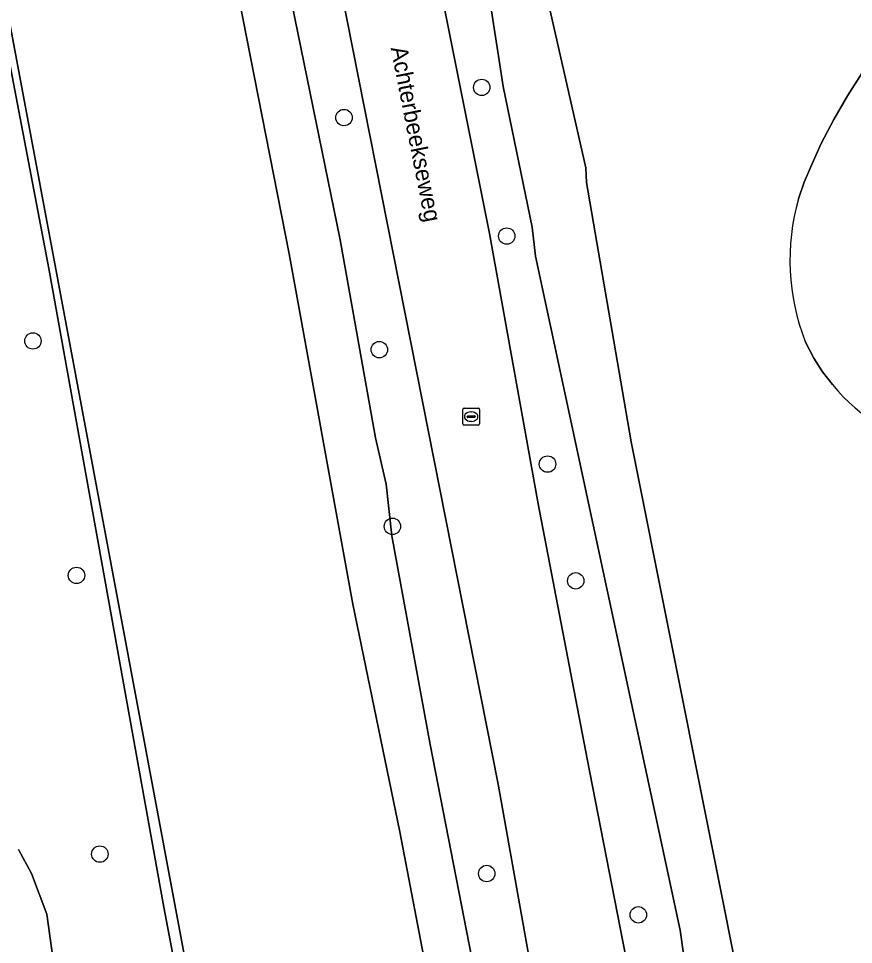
# Model space of a CAD drawing. Extents: x 162156 to 163172, y 378995 to 380779.
# Drawn here: x 162546.7 to 162596.4, y 380059.6 to 380114.8 of the extents above; entities that cross this region are included whole.
import ezdxf

# ---------------------------------------------------------------- set-up
doc = ezdxf.new("R2010")
doc.units = 0
for name, color, linetype in [('IMGEO_Boom', 7, 'Continuous'), ('IMGEO_Gemengd_bos', 7, 'Continuous'), ('IMGEO_Groenvoorziening', 7, 'Continuous'), ('IMGEO_Haag', 7, 'Continuous'), ('IMGEO_Hek', 7, 'Continuous'), ('IMGEO_Naaldbos', 7, 'Continuous'), ('IMGEO_Oever', 7, 'Continuous'), ('IMGEO_Openbare_ruimte_label', 7, 'Continuous'), ('IMGEO_Rijbaan_lokaal_gesloten', 7, 'Continuous'), ('IMGEO_Rioolput', 7, 'Continuous'), ('IMGEO_Waterloop', 7, 'Continuous')]:
    doc.layers.add(name, color=color, linetype=linetype)

msp = doc.modelspace()

# ---------------------------------------------------------------- linework, layer by layer
at = {"layer": 'IMGEO_Boom'}
for centre in [(162574.286, 380110.709), (162566.08, 380108.914), (162575.776, 380101.85), (162547.551, 380095.602), (162568.184, 380095.083), (162578.206, 380088.263), (162568.966, 380084.554), (162550.147, 380081.63), (162579.886, 380081.308), (162551.539, 380065.024), (162574.583, 380063.867), (162583.614, 380061.406)]:
    msp.add_circle(centre, 0.489, dxfattribs=at)
at = {"layer": 'IMGEO_Gemengd_bos'}
msp.add_lwpolyline([(162400.676, 380179.495), (162398.885, 380166.778), (162395.898, 380167.057), (162392.478, 380150.856), (162392.853, 380150.861), (162540.594, 380144.237), (162564.82, 380014.925), (162572.225, 380017.602), (162572.762, 380015.892), (162579.568, 380018.869), (162579.377, 380030.164), (162578.952, 380032.272), (162578.334, 380034.982), (162578.153, 380034.742), (162576.774, 380034.424), (162575.515, 380034.385), (162569.404, 380066.345), (162566.616, 380079.925), (162562.818, 380100.799), (162551.295, 380159.407)], dxfattribs=at)
at = {"layer": 'IMGEO_Groenvoorziening'}
for points in [[(162553.893, 380161.352), (162557.923, 380140.391), (162565.847, 380101.637), (162567.964, 380089.822), (162568.602, 380087.062), (162568.939, 380083.982), (162571.207, 380071.562), (162578.334, 380034.982), (162578.952, 380032.272), (162579.377, 380030.164), (162579.568, 380018.869)], [(162563.225, 380159.104), (162564.808, 380151.789), (162574.757, 380102.003), (162577.654, 380085.891), (162580.561, 380070.692), (162585.484, 380045.475), (162586.952, 380037.951), (162587.49, 380036.291)], [(162577.489, 380100.646), (162577.297, 380102.376), (162575.561, 380110.772), (162574.052, 380120.585), (162572.567, 380127.281), (162568.894, 380145.781), (162566.707, 380157.777)], [(162548.501, 380099.916), (162540.141, 380143.694), (162500, 380145.569), (162434.018, 380148.502), (162434.2, 380139.109), (162437.457, 380138.118), (162442.036, 380138.744), (162442.142, 380139.402), (162478.697, 380143.382), (162479.015, 380133.38), (162480.438, 380125.638), (162483.494, 380126.101), (162484.787, 380126.16)], [(162583.583, 380025.203), (162581.624, 380035.618), (162579.642, 380046.158), (162577.392, 380057.278), (162575.263, 380069.198), (162560.346, 380144.642)], [(162590.389, 380037.567), (162588.955, 380045.327), (162586.944, 380054.568), (162586.109, 380060.488), (162577.489, 380100.646)], [(162546.694, 380065.309), (162547.466, 380063.866), (162548.39, 380061.445), (162555.125, 380012.725), (162562.863, 380015.299), (162563.634, 380012.87), (162564.602, 380013.135), (162555.349, 380061.863), (162548.501, 380099.916)], [(162556.197, 380009.943), (162557.25, 380010.193), (162563.329, 380012.388), (162563.228, 380012.759), (162563.634, 380012.87), (162562.863, 380015.299), (162555.125, 380012.725), (162548.39, 380061.445), (162547.466, 380063.866), (162546.694, 380065.309)]]:
    msp.add_lwpolyline(points, dxfattribs=at)
msp.add_lwpolyline([(162540.594, 380144.237), (162392.853, 380150.861), (162392.478, 380150.856), (162392.372, 380150.353), (162434.018, 380148.502), (162500, 380145.569), (162540.141, 380143.694), (162548.501, 380099.916), (162555.349, 380061.863), (162564.602, 380013.135), (162564.772, 380013.181), (162564.864, 380012.844), (162565.189, 380012.97), (162565.117, 380013.339), (162564.82, 380014.925)], close=True, dxfattribs=at)
at = {"layer": 'IMGEO_Haag'}
msp.add_lwpolyline([(162540.594, 380144.237), (162392.853, 380150.861), (162392.478, 380150.856), (162392.372, 380150.353), (162434.018, 380148.502), (162500, 380145.569), (162540.141, 380143.694), (162548.501, 380099.916), (162555.349, 380061.863), (162564.602, 380013.135), (162564.772, 380013.181), (162564.864, 380012.844), (162565.189, 380012.97), (162565.117, 380013.339), (162564.82, 380014.925)], close=True, dxfattribs=at)
at = {"layer": 'IMGEO_Hek'}
msp.add_lwpolyline([(162392.372, 380150.353), (162434.018, 380148.502), (162500, 380145.569), (162540.141, 380143.694), (162548.501, 380099.916), (162555.349, 380061.863), (162564.602, 380013.135)], dxfattribs=at)
at = {"layer": 'IMGEO_Naaldbos'}
for points in [[(162598.999, 380160.213), (162591.971, 380160.192), (162585.021, 380160.577), (162577.372, 380161.631), (162570.251, 380162.647), (162569.587, 380158.112), (162574.693, 380132.607), (162578.254, 380115.715), (162580.493, 380105.908), (162580.519, 380105.048), (162583.194, 380089.584), (162590.102, 380054.964), (162591.376, 380047.324), (162593.189, 380038.48), (162594.802, 380031.543), (162603.357, 380032.993)], [(162593.163, 380104.065), (162593.501, 380105.073), (162593.87, 380105.936), (162594.512, 380107.359), (162595.253, 380108.803), (162596.066, 380110.209), (162596.949, 380111.572), (162597.899, 380112.888), (162599.054, 380114.328)], [(162595.176, 380093), (162594.593, 380093.77), (162594.075, 380094.585), (162593.559, 380095.572)]]:
    msp.add_lwpolyline(points, dxfattribs=at)
for centre, radius, start, end in [((162605.804, 380100.399), 13.162, 163.826, 201.5131), ((162604.151, 380100.411), 11.64, 219.5455, 257.5947)]:
    msp.add_arc(centre, radius, start, end, dxfattribs=at)
at = {"layer": 'IMGEO_Oever'}
for points in [[(162599.054, 380114.328), (162597.899, 380112.888), (162596.949, 380111.572), (162596.066, 380110.209), (162595.253, 380108.803), (162594.512, 380107.359), (162593.87, 380105.936), (162593.501, 380105.073), (162593.163, 380104.065)], [(162593.559, 380095.572), (162594.075, 380094.585), (162594.593, 380093.77), (162595.176, 380093)]]:
    msp.add_lwpolyline(points, dxfattribs=at)
for centre, radius, start, end in [((162605.804, 380100.399), 13.162, 163.826, 201.5131), ((162604.151, 380100.411), 11.64, 219.5455, 257.5947)]:
    msp.add_arc(centre, radius, start, end, dxfattribs=at)
at = {"layer": 'IMGEO_Rijbaan_lokaal_gesloten'}
for points in [[(162557.148, 380161.837), (162560.346, 380144.642), (162575.263, 380069.198), (162577.392, 380057.278), (162579.642, 380046.158), (162581.624, 380035.618), (162583.583, 380025.203)], [(162587.49, 380036.291), (162586.952, 380037.951), (162585.484, 380045.475), (162580.561, 380070.692), (162577.654, 380085.891), (162574.757, 380102.003), (162564.808, 380151.789), (162563.225, 380159.104)]]:
    msp.add_lwpolyline(points, dxfattribs=at)
at = {"layer": 'IMGEO_Rioolput'}
for p, q in [((162573.156, 380090.666), (162573.156, 380091.518)), ((162573.231, 380091.592), (162574.083, 380091.592)), ((162574.157, 380091.518), (162574.157, 380090.666)), ((162573.415, 380091.086), (162573.415, 380091.098)), ((162573.853, 380091.049), (162573.455, 380091.049)), ((162573.458, 380091.135), (162573.856, 380091.135)), ((162573.644, 380091.372), (162573.669, 380091.372)), ((162573.899, 380091.098), (162573.899, 380091.086)), ((162574.083, 380090.592), (162573.231, 380090.592)), ((162573.667, 380090.812), (162573.642, 380090.812))]:
    msp.add_line(p, q, dxfattribs=at)
for points in [[(162573.156, 380090.666), (162573.156, 380091.518)], [(162573.231, 380091.592), (162574.083, 380091.592)], [(162574.157, 380091.518), (162574.157, 380090.666)], [(162574.083, 380090.592), (162573.231, 380090.592)]]:
    msp.add_lwpolyline(points, dxfattribs=at)
for centre, radius, start, end in [((162573.233, 380091.516), 0.0765, 91.552, 178.448), ((162573.233, 380091.516), 0.0765, 91.552, 178.448), ((162574.081, 380091.516), 0.0765, 1.552, 88.448), ((162574.081, 380091.516), 0.0765, 1.552, 88.448), ((162573.455, 380091.095), 0.0403, 85.8775, 175.7526), ((162573.452, 380091.085), 0.0366, 178.938, 274.7102), ((162573.856, 380091.092), 0.043, 264.8664, 352.4533), ((162573.86, 380091.097), 0.0386, 1.7309, 96.639), ((162573.233, 380090.668), 0.0765, 181.552, 268.448), ((162573.233, 380090.668), 0.0765, 181.552, 268.448), ((162574.081, 380090.668), 0.0765, 271.552, 358.448), ((162574.081, 380090.668), 0.0765, 271.552, 358.448)]:
    msp.add_arc(centre, radius, start, end, dxfattribs=at)
for centre, major_axis, ratio, start_param, end_param in [((162573.643, 380091.092), (-0.387, 0.002), 0.722429, 4.712389, 7.853982), ((162573.668, 380091.092), (-0.39, 0.002), 0.717154, 1.570796, 4.712389)]:
    msp.add_ellipse(centre, major_axis=major_axis, ratio=ratio, start_param=start_param, end_param=end_param, dxfattribs=at)
at = {"layer": 'IMGEO_Waterloop'}
for points in [[(162565.847, 380101.637), (162557.923, 380140.391), (162553.893, 380161.352)], [(162551.295, 380159.407), (162562.818, 380100.799), (162566.616, 380079.925), (162569.404, 380066.345), (162575.515, 380034.385), (162576.774, 380034.424), (162578.153, 380034.742), (162578.334, 380034.982), (162571.207, 380071.562), (162568.939, 380083.982), (162568.602, 380087.062), (162567.964, 380089.822), (162565.847, 380101.637)], [(162566.707, 380157.777), (162568.894, 380145.781), (162572.567, 380127.281), (162574.052, 380120.585), (162575.561, 380110.772), (162577.297, 380102.376), (162577.489, 380100.646), (162586.109, 380060.488), (162586.944, 380054.568), (162588.955, 380045.327), (162590.389, 380037.567)], [(162593.189, 380038.48), (162591.376, 380047.324), (162590.102, 380054.964), (162583.194, 380089.584), (162580.519, 380105.048), (162580.493, 380105.908), (162578.254, 380115.715), (162574.693, 380132.607), (162569.587, 380158.112)]]:
    msp.add_lwpolyline(points, dxfattribs=at)

# ---------------------------------------------------------------- texts
at = {"layer": 'IMGEO_Openbare_ruimte_label'}
msp.add_text('Achterbeekseweg', height=1, rotation=281.1301, dxfattribs=at).set_placement((162568.859, 380113.058))

doc.saveas('drawing.dxf')
